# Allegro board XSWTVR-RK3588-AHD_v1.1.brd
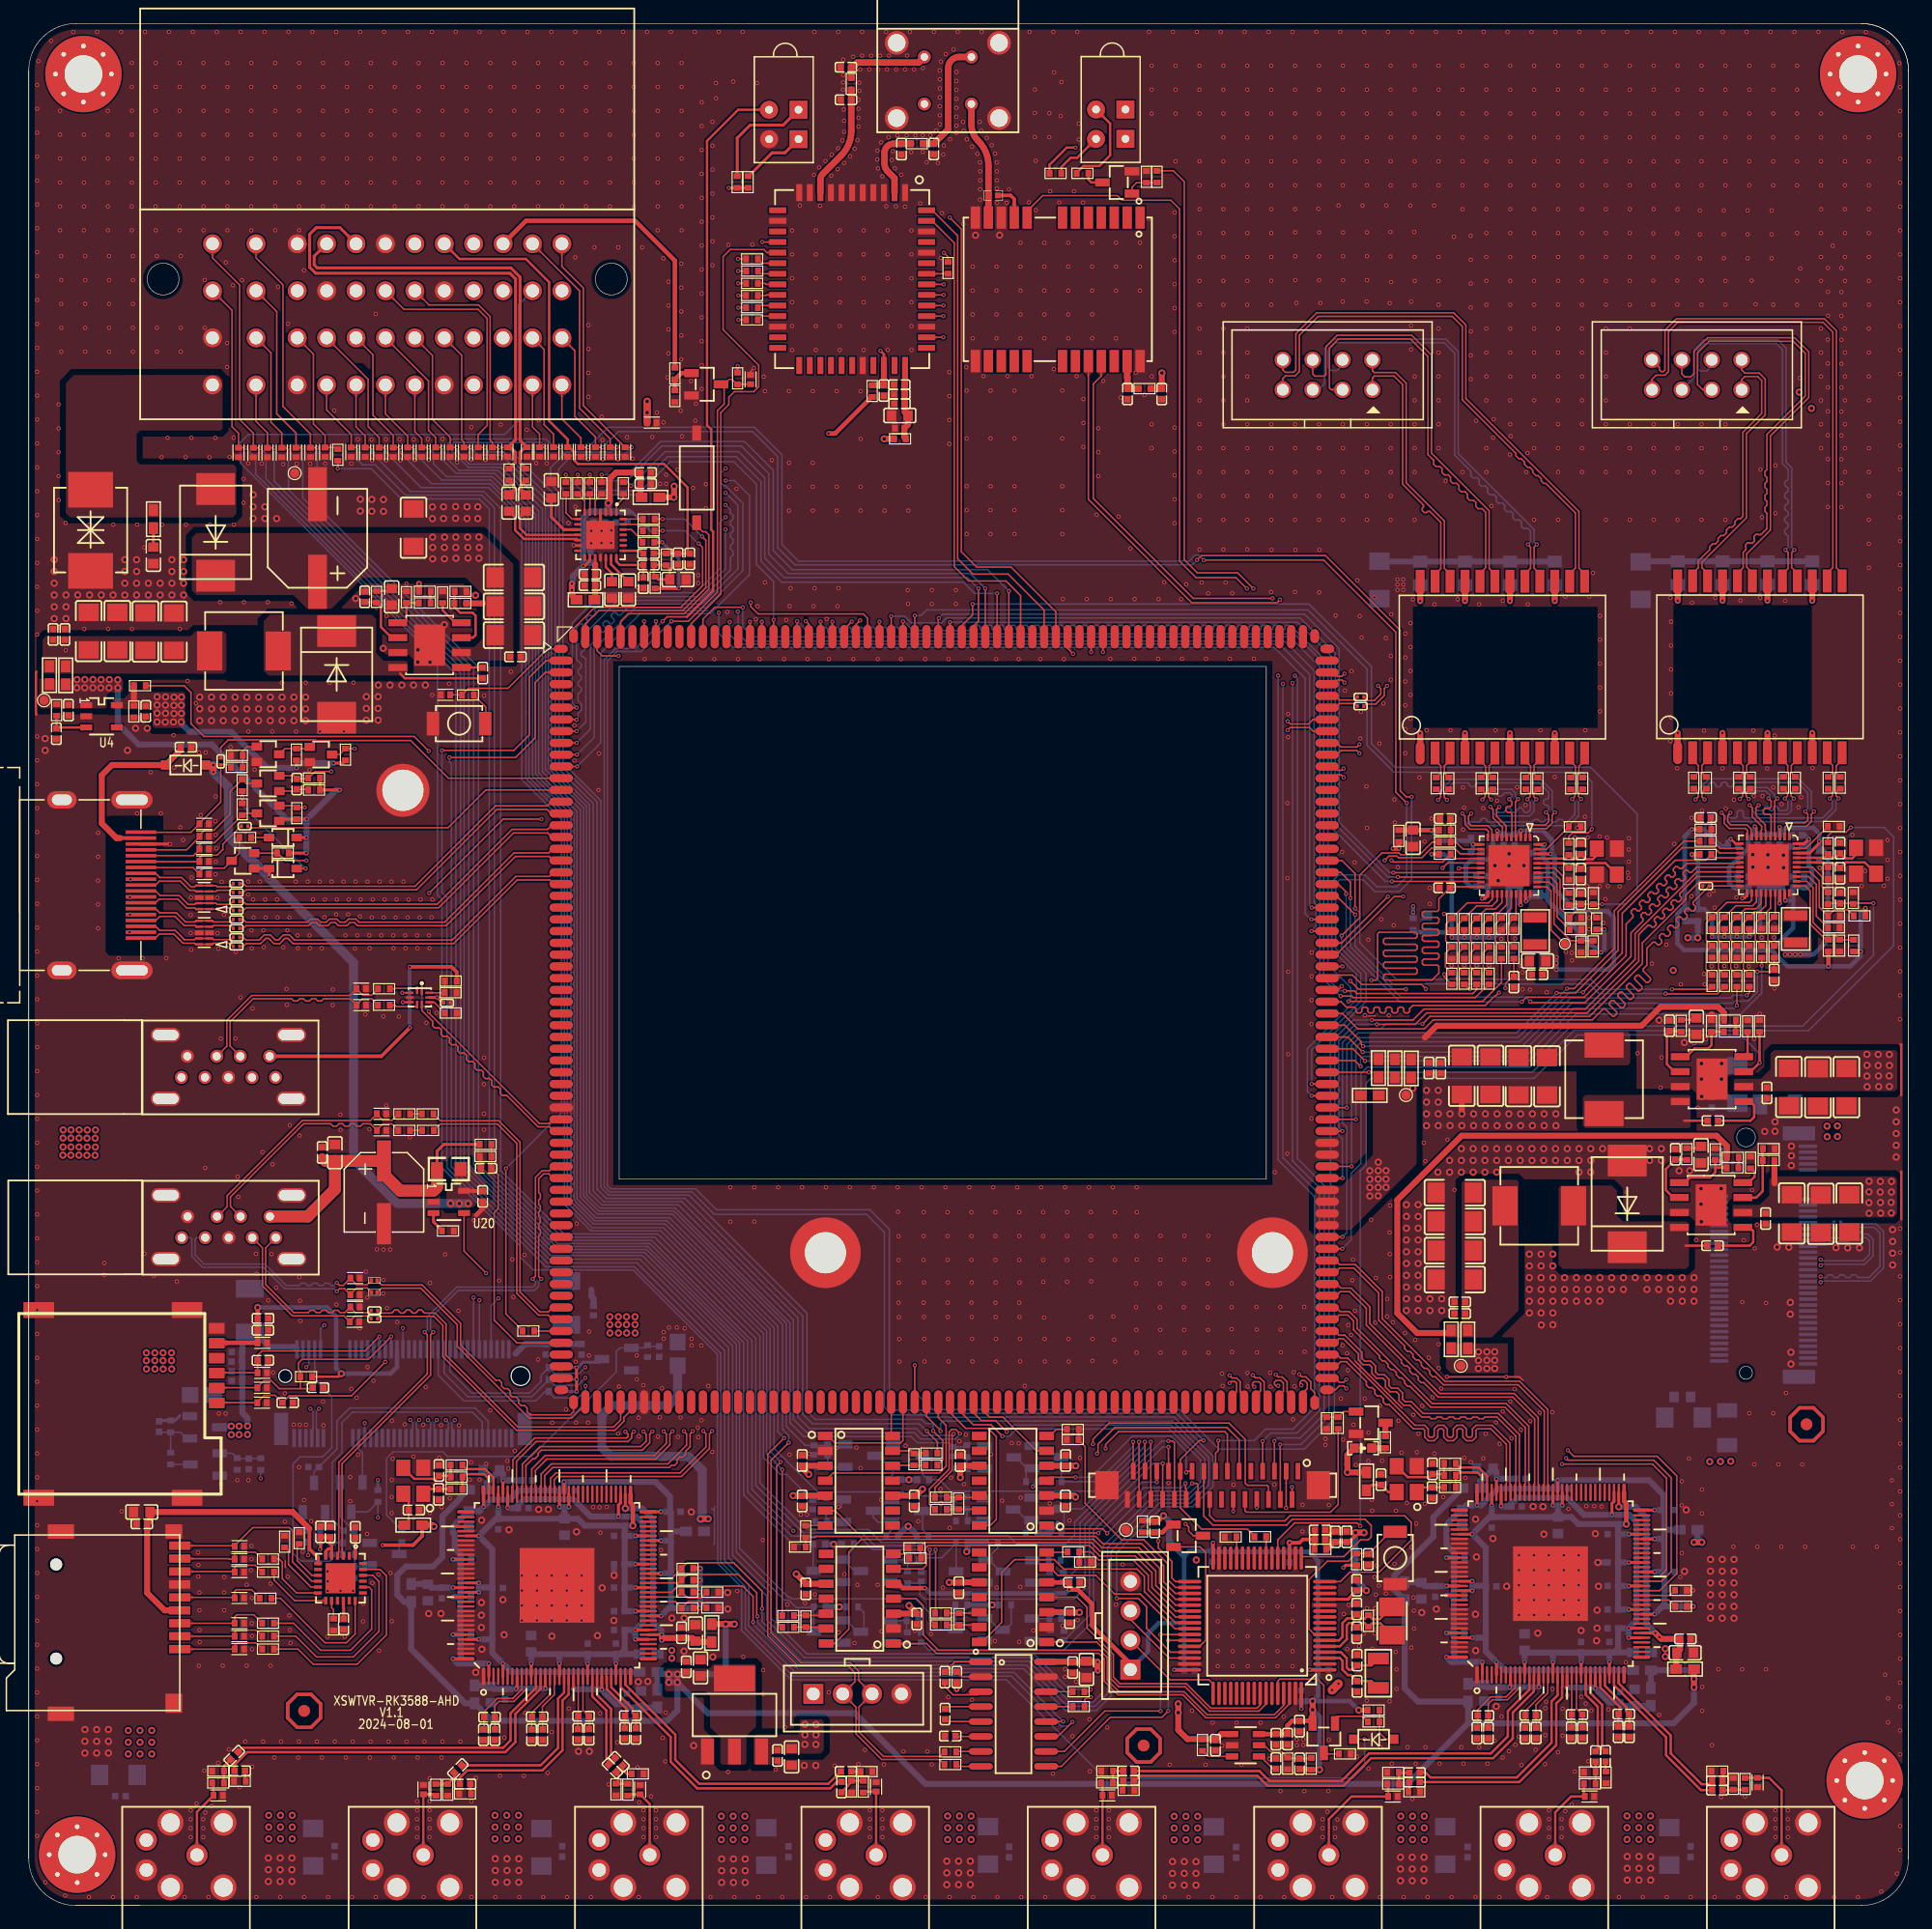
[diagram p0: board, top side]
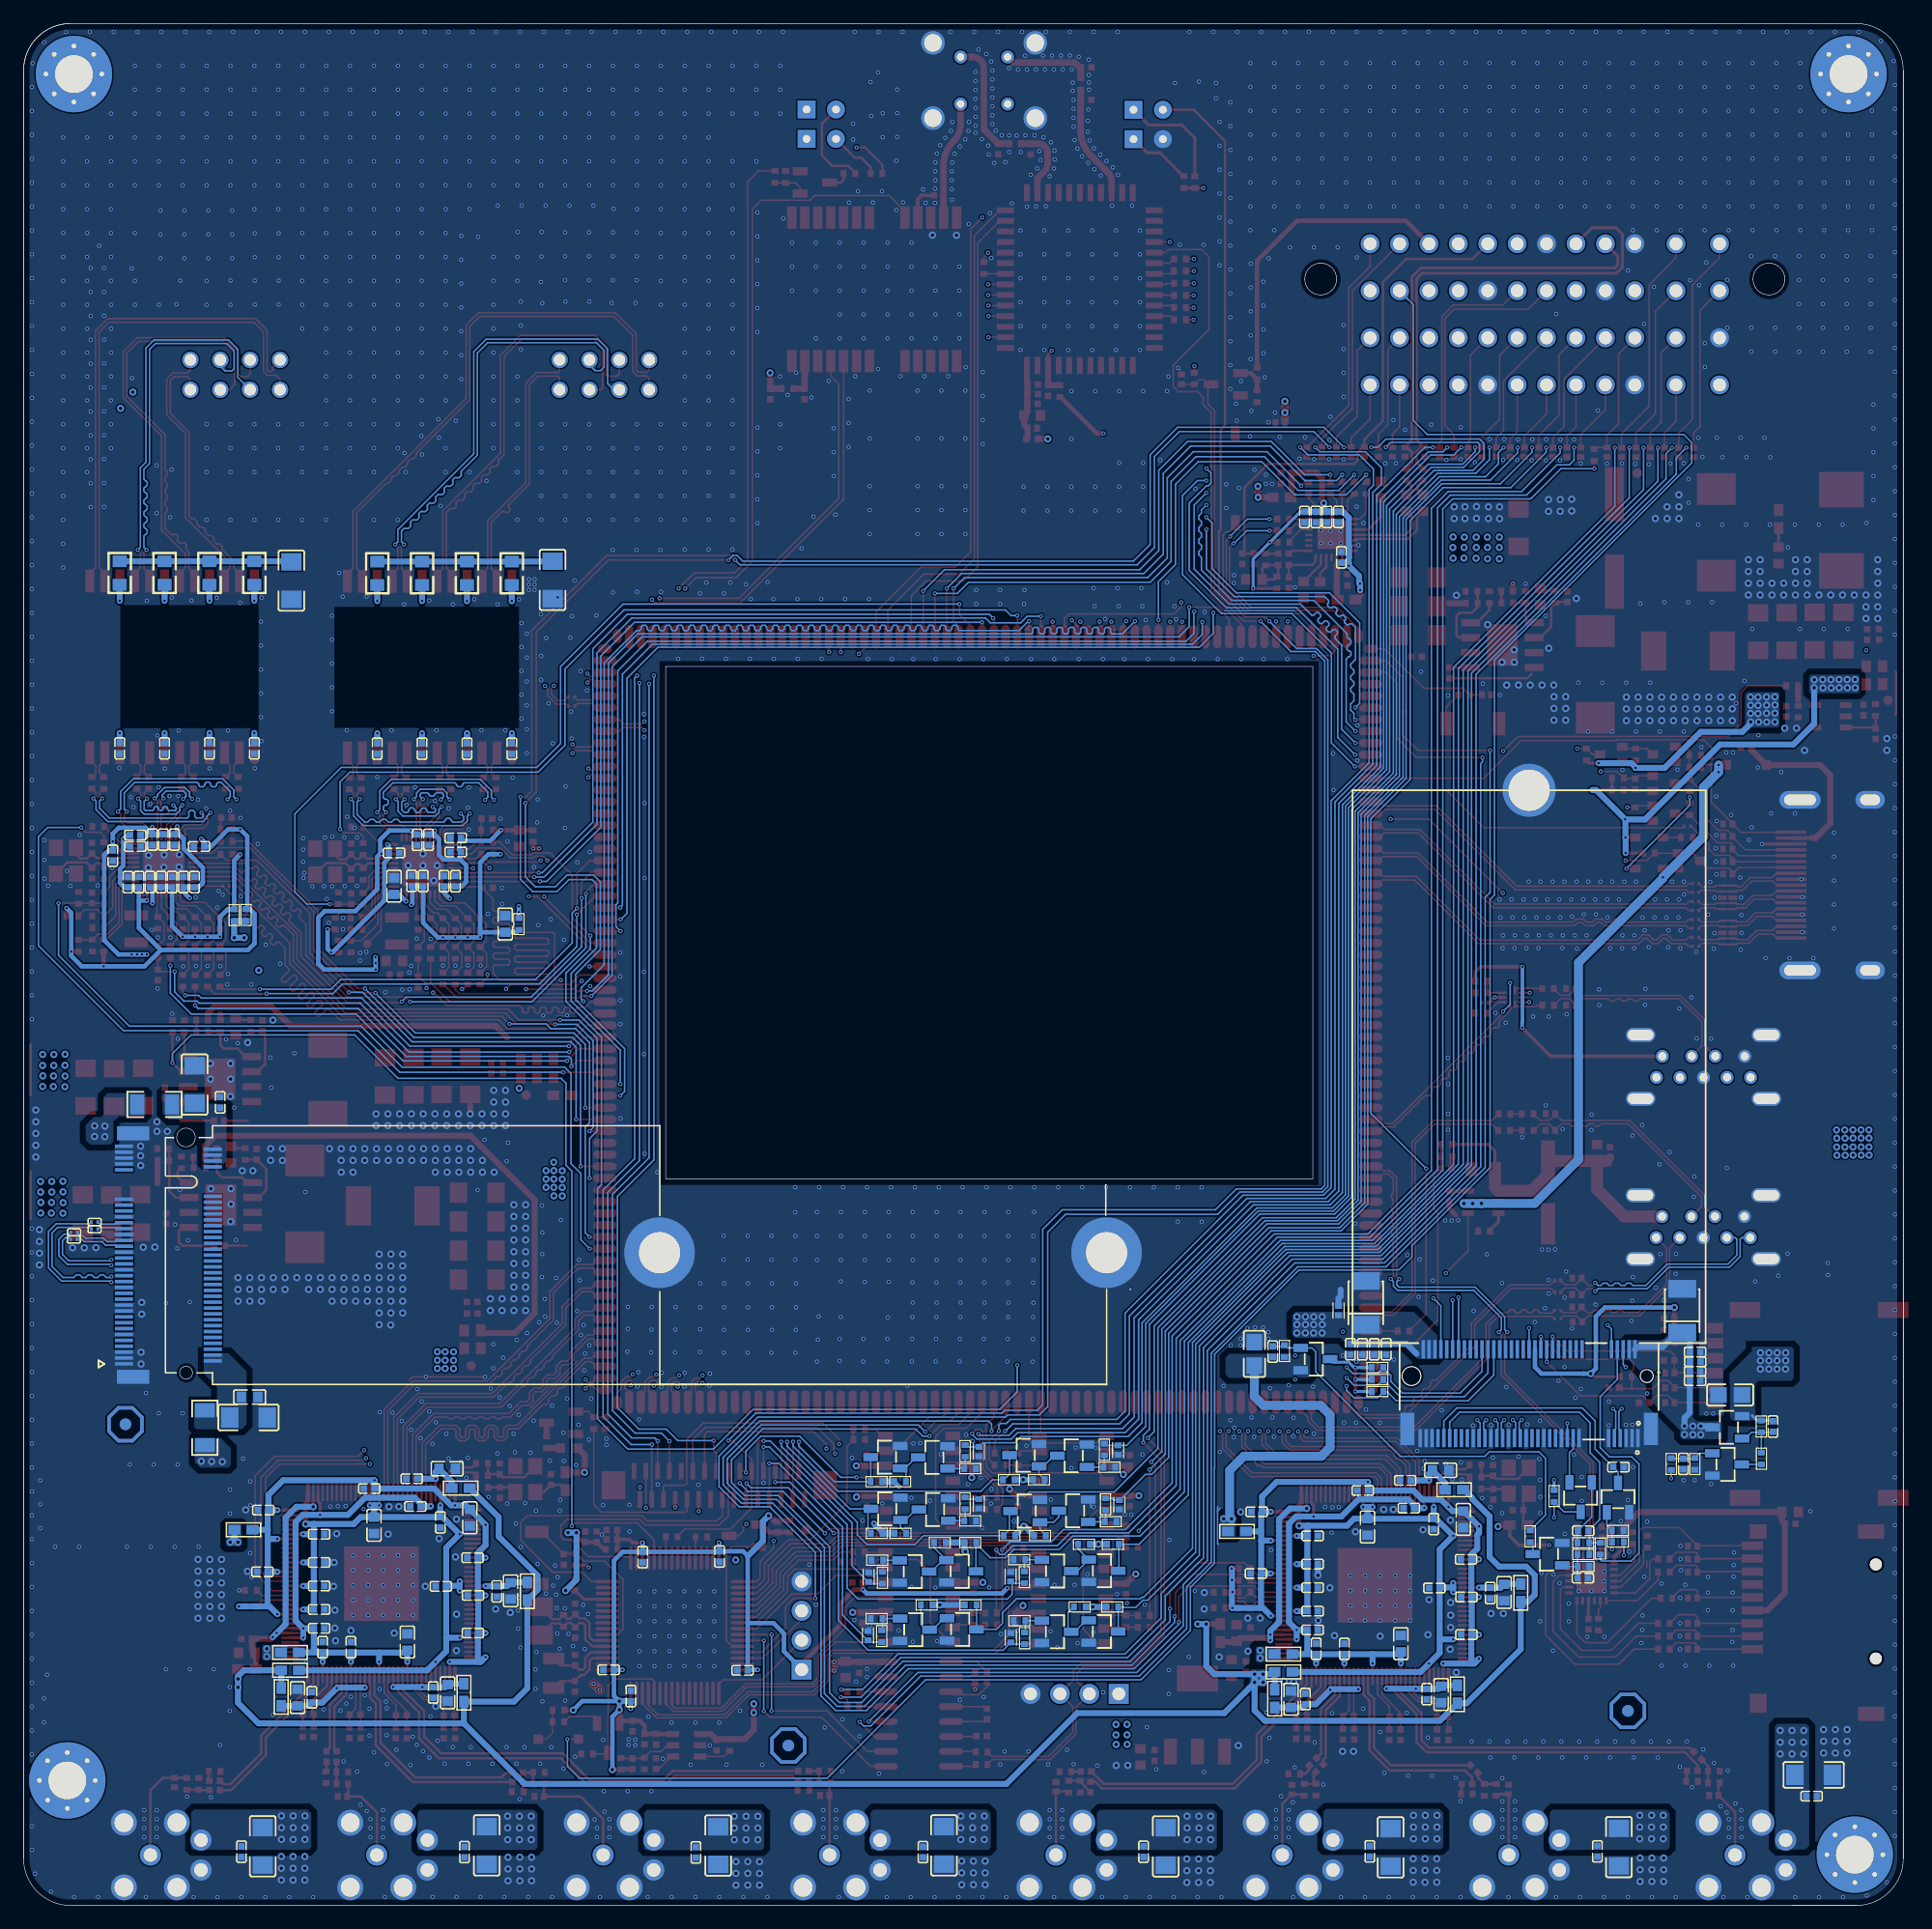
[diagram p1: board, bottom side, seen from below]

Outline 159.78 x 160 mm; copper layers: TOP, GND02, L3, POW04, GND05, BOTTOM. Coordinates in mm from the lower left corner of the outline.
Outline path: 0,156 0,4 ; 0,156 arc(1.17,158.83) 4,160 155.78,160 ; 0,156 0,4 ; 0,4 arc(1.17,1.17) 4,0 ; 4,0 9.4,0 ; 4,0 9.4,0 ; 9.4,0 155.78,0 arc(158.61,1.17) 159.78,4 ; 155.78,160 arc(158.61,158.83) 159.78,156 ; 155.78,160 arc(158.61,158.83) 159.78,156 ; 159.78,156 159.78,4 ; 159.78,156 159.78,4 ; 50.19,105.34 50.19,61.77 105.2,61.77 105.2,105.34 50.19,105.34

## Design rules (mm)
constraint set DEFAULT: min track width 0.102
net group 5G_USB: nets 5G_USB_DM 5G_USB_DP
net group HDMI0_TX0N_PORT: nets HDMI0_TX0N_PORT HDMI0_TX0N_PORT/EDP0_TX_D0N
net group HDMI0_TX0P_PORT: nets HDMI0_TX0P_PORT HDMI0_TX0P_PORT/EDP0_TX_D0P
net group HDMI0_TX1N_PORT: nets HDMI0_TX1N_PORT HDMI0_TX1N_PORT/EDP0_TX_D1N
net group HDMI0_TX1P_PORT: nets HDMI0_TX1P_PORT HDMI0_TX1P_PORT/EDP0_TX_D1P
net group HDMI0_TX2N_PORT: nets HDMI0_TX2N_PORT HDMI0_TX2N_PORT/EDP0_TX_D2N
net group HDMI0_TX2P_PORT: nets HDMI0_TX2P_PORT HDMI0_TX2P_PORT/EDP0_TX_D2P
net group HDMI0_TX3N_PORT: nets HDMI0_TX3N_PORT HDMI0_TX3N_PORT/EDP0_TX_D3N
net group HDMI0_TX3P_PORT: nets HDMI0_TX3P_PORT HDMI0_TX3P_PORT/EDP0_TX_D3P
net group LAN0_A: nets LAN0_A+ LAN0_A-
net group LAN0_B: nets LAN0_B+ LAN0_B-
net group LAN0_C: nets LAN0_C+ LAN0_C-
net group LAN0_D: nets LAN0_D+ LAN0_D-
net group LAN1_A: nets LAN1_A+ LAN1_A-
net group LAN1_B: nets LAN1_B+ LAN1_B-
net group LAN1_C: nets LAN1_C+ LAN1_C-
net group LAN1_D: nets LAN1_D+ LAN1_D-
net group N17604219: nets N17604219 N17604223
net group N17604225: nets N17604225 N17604227
net group PCIE20_0_RXN/SATA30_0_RXN: nets PCIE20_0_RXN/SATA30_0_RXN SATA0_RXN
net group PCIE20_0_RXP/SATA30_0_RXP: nets PCIE20_0_RXP/SATA30_0_RXP SATA0_RXP
net group PCIE20_0_TXN/SATA30_0_TXN: nets PCIE20_0_TXN/SATA30_0_TXN SATA0_TXN
net group PCIE20_0_TXP/SATA30_0_TXP: nets PCIE20_0_TXP/SATA30_0_TXP SATA0_TXP
net group PCIE20_2_REFCLK: nets PCIE20_2_REFCLKN PCIE20_2_REFCLKP
net group PCIE20_2_RXN/SATA30_2_RX: nets PCIE20_2_RXN/SATA30_2_RXN PCIE20_2_RXP/SATA30_2_RXP
net group PCIE20_2_TX: nets N17473177 N17473180
net group PCIE20_2_TXN/SATA30_2_TX: nets PCIE20_2_TXN/SATA30_2_TXN PCIE20_2_TXP/SATA30_2_TXP
net group PHY0_MDI0+: nets PHY0_MDI0+ PHY0_MDI_0+
net group PHY0_MDI0-: nets PHY0_MDI0- PHY0_MDI_0-
net group PHY0_MDI1+: nets PHY0_MDI1+ PHY0_MDI_1+
net group PHY0_MDI1-: nets PHY0_MDI1- PHY0_MDI_1-
net group PHY0_MDI2+: nets PHY0_MDI2+ PHY0_MDI_2+
net group PHY0_MDI2-: nets PHY0_MDI2- PHY0_MDI_2-
net group PHY0_MDI3+: nets PHY0_MDI3+ PHY0_MDI_3+
net group PHY0_MDI3-: nets PHY0_MDI3- PHY0_MDI_3-
net group PHY1_MDI0: nets PHY1_MDI0+ PHY1_MDI0-
net group PHY1_MDI1: nets PHY1_MDI1+ PHY1_MDI1-
net group PHY1_MDI2: nets PHY1_MDI2+ PHY1_MDI2-
net group PHY1_MDI3: nets PHY1_MDI3+ PHY1_MDI3-
net group PHY1_MDI_0: nets PHY1_MDI_0+ PHY1_MDI_0-
net group PHY1_MDI_1: nets PHY1_MDI_1+ PHY1_MDI_1-
net group PHY1_MDI_2: nets PHY1_MDI_2+ PHY1_MDI_2-
net group PHY1_MDI_3: nets PHY1_MDI_3+ PHY1_MDI_3-
net group SDMMC_CMD: nets N17735212 SDMMC_CMD
net group SDMMC_D0: nets N17735257 SDMMC_D0
net group SDMMC_D1: nets N17735222 SDMMC_D1
net group SDMMC_D2: nets N17735246 SDMMC_D2
net group SDMMC_D3: nets N17735210 SDMMC_D3
net group TYPEC0_OTG_DM: nets N17570124 TYPEC0_OTG_DM
net group TYPEC0_OTG_DP: nets N17570191 TYPEC0_OTG_DP
net group TYPEC0_SSRX1: nets TYPEC0_SSRX1N TYPEC0_SSRX1P
net group TYPEC0_SSTX1: nets TYPEC0_SSTX1N TYPEC0_SSTX1P
net group USB20_HOST0: nets USB20_HOST0_DM USB20_HOST0_DP
net group USB20_HOST1: nets USB20_HOST1_DM USB20_HOST1_DP
net group USB30_HOST0_SSRX: nets USB30_HOST0_SSRXN USB30_HOST0_SSRXP
net group USB30_HOST0_SSTX: nets USB30_HOST0_SSTXN USB30_HOST0_SSTXP
net group USB30_OTG0: nets USB30_OTG0_DM USB30_OTG0_DP
net group USB30_OTG1: nets DEBUG_DM0 DEBUG_DP0
net group GMAC0_RXCLK: nets GMAC0_RXCLK
net group GMAC0_RXD0: nets GMAC0_RXD0
net group GMAC0_RXD1: nets GMAC0_RXD1
net group GMAC0_RXD2: nets GMAC0_RXD2
net group GMAC0_RXD3: nets GMAC0_RXD3
net group GMAC0_RXDV_CRS: nets GMAC0_RXDV_CRS
net group GMAC1_RXCLK: nets GMAC1_RXCLK
net group GMAC1_RXD0: nets GMAC1_RXD0
net group GMAC1_RXD1: nets GMAC1_RXD1
net group GMAC1_RXD2: nets GMAC1_RXD2
net group GMAC1_RXD3: nets GMAC1_RXD3
net group GMAC1_RXDV_CRS: nets GMAC1_RXDV_CRS

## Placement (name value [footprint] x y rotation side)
C1  100nF  [C0402]  143.16 66.72 0 top
C2  47uF  [C1206]  121.81 70.54 270 top
C3  47uF  [C1206]  129.06 70.5 270 top
C4  47uF  [C1206]  124.25 70.54 270 top
C5  47uF  [C1206]  126.64 70.51 270 top
C6  1uF  [C0402]  120.02 71.2 270 top
C7  100nF  [C0402]  119.02 71.2 270 top
C8  10uF  [C1206]  154.5 69.57 270 top
C9  10uF  [C1206]  152.08 69.55 270 top
C10  10uF  [C1206]  149.62 69.59 270 top
C11  100nF  [C0402]  147.75 69.08 270 top
C12  22pF  [C0402]  139.47 74.79 90 top
C13  3.3nF  [C0603]  141.75 74.75 270 top
C14  100nF  [C0402]  38.59 104.79 90 top
C15  47uF  [C1206]  7.53 108.34 90 top
C16  47uF  [C1206]  5.09 108.34 90 top
C17  47uF  [C1206]  12.34 108.3 90 top
C18  47uF  [C1206]  9.92 108.31 90 top
C19  1uF  [C0402]  3.07 108.06 90 top
C20  100nF  [C0402]  2.07 108.06 90 top
C21  10uF  [C1206]  41.24 112.9 0 top
C22  10uF  [C1206]  41.24 110.45 0 top
C23  10uF  [C1206]  41.24 108 0 top
C24  100nF  [C0402]  41.37 106.16 0 top
C25  100nF  [C0402]  2.35 99.62 270 top
C26  10uF  [C0402]  3.37 101.63 270 top
C27  4.7uF  [C0402]  9.95 101.52 270 top
C28  47pF  [C0402]  28.56 111.26 90 top
C29  4.7nF  [C0603]  30.85 111.26 270 top
C30  100nF  [C0402]  143.13 56.1 0 top
C31  47uF  [C1206]  121.21 55.68 180 top
C32  47uF  [C1206]  121.21 58.15 180 top
C33  47uF  [C1206]  121.21 53.21 180 top
C34  47uF  [C1206]  121.21 60.6 180 top
C35  1uF  [C0402]  121.65 51.32 180 top
C36  100nF  [C0402]  121.64 50.33 180 top
C37  10uF  [C1206]  152.33 58.8 270 top
C38  10uF  [C1206]  149.87 58.84 270 top
C39  10uF  [C1206]  154.75 58.83 270 top
C40  100nF  [C0402]  147.64 58.4 270 top
C41  100UF/50V  [SMD_D8XL10_5MM]  24.55 116.26 90 top
C42  10uF  [C1206]  32.71 117.14 90 top
C43  1uF  [C0603]  10.6 114.78 270 top
C44  22pF  [C0402]  139.97 63.87 90 top
C45  3.3nF  [C0603]  142.15 63.83 270 top
C46  39pF  [C0402]  108.02 12.05 90 top
C51  10uF  [C0402]  106.02 14.14 270 top
C52  100nF  [C0402]  107 14.14 90 top
C56  10UF  [C0402]  100.87 13.63 90 top
C57  10nF  [C0402]  106.02 12.06 90 top
C60  12pF  [C0402]  112.91 18.63 270 top
C61  12pF  [C0402]  112.91 20.86 90 top
C62  100nF  [C0402]  113.86 29.43 270 top
C63  12pF  [C0402]  112.89 23.2 270 top
C64  12pF  [C0402]  112.89 25.21 90 top
C65  100nF  [C0402]  112.88 27.22 90 top
C66  100nF  [C0402]  100.62 29.67 270 bottom
C67  100nF  [C0402]  110.04 20.03 0 bottom
C68  100nF  [C0402]  108.16 17.8 90 bottom
C69  100nF  [C0402]  98.66 19.99 0 bottom
C70  100nF  [C0402]  107.15 29.62 270 bottom
C71  1uF  [C0402]  109.77 31.92 0 top
C72  100nF  [C0402]  109.77 31.12 0 top
C73  100nF  [C0402]  112.04 31.34 90 top
C74  1uF  [C0402]  111.07 31.34 90 top
C75  100nF  [C0402]  75.49 24.35 270 top
C76  100nF  [C0402]  108.02 15.25 90 top
C79  220UF/6.3V  [T_3528]  18.79 50.57 90 bottom
C80  10pF  [C0402]  17.68 46.24 0 bottom
C81  33pF  [C0402]  17.7 47.06 0 bottom
C82  100nF  [C0402]  17.7 45.41 0 bottom
C83  1uF  [C0402]  17.7 44.61 0 bottom
C84  10nF  [C0402]  24.21 37.27 0 bottom
C85  220nF  [C0201]  113.21 101.97 0 top
C86  220nF  [C0201]  113.21 102.75 0 top
C87  10pF  [C0402]  43.95 47.29 270 bottom
C88  1uF  [C0402]  47 47.29 270 bottom
C89  220UF/6.3V  [T_3528]  45.69 51.23 90 bottom
C91  33pF  [C0402]  44.96 47.29 270 bottom
C92  100nF  [C0402]  45.97 47.29 270 bottom
C96  100nF  [C0402]  19.91 48.91 0 top
C97  33pF  [C0402]  19.91 49.91 0 top
C98  33pF  [C0402]  19.9 46.35 0 top
C99  33pF  [C0402]  24.59 44.02 0 top
C100  33pF  [C0402]  22.01 42.75 0 top
C105  10uF  [C0805]  14.71 43.4 0 bottom
C106  100nF  [C0402]  11.08 40.72 270 bottom
C107  10uF  [C0805]  55.16 46.89 90 bottom
C108  100nF  [C0402]  53.59 47.09 90 bottom
C109  100nF  [C0402]  18.7 37.54 270 bottom
C110  100nF  [C0402]  27.24 27.83 180 bottom
C111  100nF  [C0402]  117.8 11.29 0 top
C112  100nF  [C0402]  143.53 10.6 180 top
C113  100nF  [C0402]  123.1 14.65 90 top
C114  100nF  [C0402]  123.62 16.15 0 top
C115  100nF  [C0402]  127.66 16.18 0 top
C116  100nF  [C0402]  128.14 14.66 90 top
C117  100nF  [C0402]  131.12 14.69 90 top
C118  100nF  [C0402]  131.61 16.23 0 top
C119  100nF  [C0402]  93.49 11.43 0 top
C120  100nF  [C0402]  93.49 10.63 0 top
C121  100nF  [C0402]  117.8 10.49 0 top
C122  100nF  [C0402]  133.18 12.66 90 top
C123  100nF  [C0402]  134.03 12.67 90 top
C124  100nF  [C0402]  143.53 9.81 180 top
C125  100nF  [C0402]  114.94 36.21 90 top
C126  100nF  [C0402]  127.19 14.66 90 top
C127  100nF  [C0402]  124.07 14.66 90 top
C128  100nF  [C0402]  135.11 14.77 90 top
C129  100nF  [C0402]  132.08 14.69 90 top
C130  100nF  [C0402]  135.58 16.27 0 top
C131  15pF/NC  [C0402]  119.29 35.1 270 top
C132  15pF/NC  [C0402]  119.31 37.12 90 top
C133  100nF  [C0402]  136.06 14.77 90 top
C134  10uF  [C0603]  64.84 12.63 270 top
C135  100nF  [C0402]  63.65 12.75 270 top
C136  100nF  [C0402]  55.89 20.29 90 top
C137  10uF  [C0603]  57.1 20.2 90 top
C138  10uF  [C0603]  127.16 22.4 90 bottom
C139  100nF  [C0402]  134.65 23.56 180 bottom
C140  100nF  [C0402]  134.36 21.96 90 bottom
C141  100nF  [C0402]  126.47 33.92 0 bottom
C142  100nF  [C0402]  131.96 21.95 90 bottom
C143  10uF  [C0603]  121.85 32.97 270 bottom
C144  100nF  [C0402]  121.58 26.36 0 bottom
C145  100nF  [C0402]  130.4 35.44 0 bottom
C146  100nF  [C0402]  139.47 28.36 0 bottom
C147  100nF  [C0402]  121.61 29.56 0 bottom
C148  100nF  [C0402]  121.58 23.16 0 bottom
C149  100nF  [C0402]  139.4 33.61 0 bottom
C150  10uF  [C0603]  123.77 37.14 180 bottom
C151  100nF  [C0402]  126.78 36.28 0 bottom
C152  10uF  [C0603]  118.38 26.75 270 bottom
C153  100nF  [C0402]  119.56 26.7 270 bottom
C154  10uF  [C0603]  129.99 32.32 270 bottom
C155  100nF  [C0402]  134.65 29.16 180 bottom
C156  100nF  [C0402]  124.3 27.13 0 bottom
C157  100nF  [C0402]  124.36 32.57 270 bottom
C158  100nF  [C0402]  134.65 25.16 180 bottom
C159  100nF  [C0402]  134.65 27.16 180 bottom
C160  100nF  [C0402]  134.65 31.56 180 bottom
C161  10uF  [C0603]  123.73 18.08 270 bottom
C162  100nF  [C0402]  124.95 18.11 270 bottom
C163  10uF  [C0603]  136.49 17.67 90 bottom
C164  100nF  [C0402]  135.27 17.7 90 bottom
C165  10uF  [C0603]  140.8 21.48 0 top
C166  100nF  [C0402]  140.81 22.66 0 top
C167  100nF  [C0402]  83.33 4.54 270 bottom
C168  47uF  [C1206]  81.54 5.11 270 bottom
C169  100nF  [C0402]  102.63 4.51 270 bottom
C170  47uF  [C1206]  100.73 5.1 270 bottom
C171  100nF  [C0402]  122.3 4.54 270 bottom
C172  47uF  [C1206]  120.41 5.1 270 bottom
C173  100nF  [C0402]  141.26 4.57 270 bottom
C174  47uF  [C1206]  139.45 5.03 270 bottom
C175  100nF  [C0402]  17.47 12.73 45 top
C176  100nF  [C0402]  17.94 11.45 180 top
C177  100nF  [C0402]  36.48 11.6 45 top
C178  100nF  [C0402]  37.09 10.32 180 top
C179  100nF  [C0402]  50.17 12.22 135 top
C180  100nF  [C0402]  69.1 10.07 90 top
C181  100nF  [C0402]  39.17 16.01 0 top
C182  100nF  [C0402]  42.74 14.52 90 top
C183  100nF  [C0402]  43.22 16.04 0 top
C184  100nF  [C0402]  43.69 14.52 90 top
C185  100nF  [C0402]  47.16 16.09 0 top
C186  100nF  [C0402]  49.61 11.67 135 top
C187  100nF  [C0402]  69.47 11.4 180 top
C188  100nF  [C0402]  38.65 14.51 90 top
C189  100nF  [C0402]  39.62 14.52 90 top
C190  100nF  [C0402]  46.67 14.55 90 top
C191  100nF  [C0402]  32.74 33.62 0 top
C192  100nF  [C0402]  47.63 14.55 90 top
C193  100nF  [C0402]  50.66 14.63 90 top
C194  100nF  [C0402]  51.14 16.13 0 top
C195  100nF  [C0402]  51.61 14.63 90 top
C196  15pF/NC  [C0402]  34.84 34.96 270 top
C197  15pF/NC  [C0402]  34.87 36.99 90 top
C198  10uF  [C0603]  42.71 22.26 90 bottom
C199  100nF  [C0402]  47.51 21.81 90 bottom
C200  100nF  [C0402]  50.2 23.42 180 bottom
C201  100nF  [C0402]  42.03 33.78 0 bottom
C202  100nF  [C0402]  49.91 21.82 90 bottom
C203  10uF  [C0603]  37.4 32.83 270 bottom
C204  100nF  [C0402]  37.13 26.22 0 bottom
C205  100nF  [C0402]  54.95 33.47 0 bottom
C206  100nF  [C0402]  37.16 29.42 0 bottom
C207  100nF  [C0402]  45.94 35.28 0 bottom
C208  100nF  [C0402]  37.14 23.02 0 bottom
C209  100nF  [C0402]  55.03 28.22 0 bottom
C210  10uF  [C0603]  39.28 17.94 270 bottom
C211  100nF  [C0402]  40.5 17.97 270 bottom
C212  10uF  [C0603]  33.93 26.61 270 bottom
C213  100nF  [C0402]  35.11 26.56 270 bottom
C214  10uF  [C0603]  45.54 32.18 270 bottom
C215  100nF  [C0402]  39.91 32.43 270 bottom
C216  100nF  [C0402]  50.2 27.02 180 bottom
C217  100nF  [C0402]  50.2 29.02 180 bottom
C218  100nF  [C0402]  39.86 26.99 0 bottom
C219  100nF  [C0402]  50.2 31.42 180 bottom
C220  100nF  [C0402]  50.2 25.02 180 bottom
C221  10uF  [C0603]  52.04 17.53 90 bottom
C222  100nF  [C0402]  50.82 17.56 90 bottom
C223  10uF  [C0603]  56.67 23.17 90 top
C224  100nF  [C0402]  55.49 23.19 90 top
C225  10uF  [C0603]  39.32 37 180 bottom
C226  100nF  [C0402]  42.33 36.14 0 bottom
C227  100nF  [C0402]  7.79 9.3 180 bottom
C228  47uF  [C1206]  7.62 11.1 180 bottom
C229  100nF  [C0402]  26 4.6 270 bottom
C230  47uF  [C1206]  24.17 4.96 270 bottom
C231  100nF  [C0402]  45.35 4.6 270 bottom
C232  47uF  [C1206]  43.58 4.94 270 bottom
C233  100nF  [C0402]  64.58 4.57 270 bottom
C234  47uF  [C1206]  62.69 5.02 270 bottom
C235  220nF  [C0201]  17.66 81.55 180 top
C236  220nF  [C0201]  17.66 82.31 180 top
C237  220nF  [C0201]  17.66 83.07 180 top
C238  220nF  [C0201]  17.66 83.83 180 top
C239  220nF  [C0201]  17.66 84.59 180 top
C240  220nF  [C0201]  17.66 85.36 180 top
C241  220nF  [C0201]  17.66 86.12 180 top
C242  220nF  [C0201]  17.66 86.88 180 top
C243  100pF  [C0402]  22.79 95.34 90 top
C244  1uF  [C0402]  13.36 98.48 0 top
C245  1uF  [C0201]  18.35 91.76 180 top
C246  1uF  [C0201]  16.32 97.27 270 top
C247  22uF  [C0603]  74.05 126.67 180 top
C248  100nF  [C0402]  74 129.29 180 top
C249  100pF  [C0402]  74.02 127.67 180 top
C250  10pF  [C0402]  74 128.49 180 top
C251  NC  [C0402]  69.47 153.51 180 top
C252  NC  [C0402]  69.46 156.29 180 top
C253  NC  [C0402]  74.18 149.32 270 top
C254  NC  [C0402]  76.93 149.34 270 top
C255  4.7uF  [C0402]  72.69 128.8 270 top
C256  100nF  [C0402]  93.4 128.5 90 top
C257  100nF  [C0402]  96.31 128.5 90 top
C258  18pF  [C0402]  131.93 89.82 90 top
C259  18pF  [C0402]  131.93 87.69 270 top
C260  10nF  [C0402]  118.27 98.35 270 bottom
C261  10nF  [C0402]  122.08 98.35 270 bottom
C262  10nF  [C0402]  125.9 98.35 270 bottom
C263  10nF  [C0402]  129.71 98.35 270 bottom
C264  DNP  [C0402]  131.93 85.58 90 top
C265  1000pF  [C1206]  114.81 112.7 270 bottom
C266  4.7uF  [C0603]  118.84 83.44 90 bottom
C267  1uF  [C0402]  125.81 87.1 90 bottom
C268  100nF  [C0402]  126.8 87.11 90 bottom
C269  4.7uF  [C0603]  117.67 90.73 270 top
C270  100nF  [C0402]  123.04 90.76 0 bottom
C271  100nF  [C0402]  123.04 89.56 0 bottom
C272  4.7uF  [C0603]  128.29 86.66 90 bottom
C273  100nF  [C0402]  128.29 89.49 180 bottom
C274  3pF  [C0402]  120.35 86.52 180 top
C275  4.7uF  [C0603]  128.26 80.3 180 top
C276  100nF  [C0402]  128.22 79.14 180 top
C277  100nF  [C0402]  124.03 87.09 90 bottom
C278  100nF  [C0402]  120.39 92.4 180 top
C279  100nF  [C0402]  125.36 90.6 270 bottom
C280  100nF  [C0402]  126.32 90.6 270 bottom
C281  100nF  [C0402]  123.07 87.09 90 bottom
C282  DNP  [C0402]  126.25 78.51 270 top
C283  18pF  [C0402]  153.96 89.89 90 top
C284  18pF  [C0402]  153.96 87.76 270 top
C285  10nF  [C0402]  140.16 98.38 270 bottom
C286  10nF  [C0402]  143.97 98.38 270 bottom
C287  10nF  [C0402]  147.79 98.38 270 bottom
C288  10nF  [C0402]  151.6 98.38 270 bottom
C289  DNP  [C0402]  153.96 85.65 90 top
C290  1000pF  [C1206]  137.01 112.64 270 bottom
C291  4.7uF  [C0402]  148.09 87.01 90 bottom
C292  1uF  [C0402]  147.15 87.01 90 bottom
C293  100nF  [C0402]  149.03 87.01 90 bottom
C294  4.7uF  [C0402]  144.86 90.04 0 bottom
C295  100nF  [C0402]  150.28 91 180 bottom
C296  100nF  [C0402]  149.97 87.01 90 bottom
C297  3pF  [C0201]  142.56 86.67 180 top
C298  4.7uF  [C0402]  150.91 87.01 90 bottom
C299  100nF  [C0402]  150.28 90.04 180 bottom
C300  100nF  [C0402]  142.53 92.49 180 top
C301  4.7uF  [C0402]  146.19 87.01 90 bottom
C302  100nF  [C0402]  147.89 90.62 270 bottom
C303  100nF  [C0402]  146.95 90.62 270 bottom
C304  DNP  [C0402]  148.36 79.11 270 top
C305  100nF  [C0402]  148.83 90.62 270 bottom
C306  100nF  [C0402]  152.2 89.25 270 bottom
C307  100nF  [C0402]  145.25 87.01 90 bottom
C308  1uF  [C0402]  38.58 60.29 270 top
C309  100nF  [C0201]  29.38 49.89 180 top
C310  120uF  [SMD_D6_3XL7_7]  30.19 60.63 270 top
C311  10uF  [C0603]  26.03 64 90 top
C312  100nF  [C0402]  24.94 64.02 90 top
C313  100nF  [C0201]  29.38 50.59 180 top
C314  100nF  [C0402]  38.88 62.67 180 top
C321  100nF  [C0402]  25.61 31.75 90 top
C322  4.7uF  [C0402]  24.81 31.76 90 top
C323  10uF  [C0603]  9.61 33.45 180 top
C324  100nF  [C0402]  9.61 32.44 180 top
C325  10uF  [C0603]  55.19 112.73 0 top
C326  1uF  [C0402]  52.69 114.94 180 top
C327  100pF  [C0402]  56.19 114.49 270 top
C328  1uF  [C0402]  52.24 112.46 90 top
C329  1uF  [C0402]  52.69 113.97 180 top
C330  8.2pF  [C0402]  55.2 114.49 270 top
C331  4.7uF  [C0402]  49.94 118.05 270 bottom
C332  100nF  [C0402]  50.9 118.04 270 bottom
C333  100nF  [C0402]  47.76 114.62 90 bottom
C334  100nF  [C0402]  47.7 113.18 180 top
C335  4.7uF  [C0402]  47.7 112.22 180 top
C336  4.7uF  [C0402]  48.01 118.05 270 bottom
C337  100nF  [C0402]  48.98 118.05 270 bottom
C338  10uF  [C0603]  50.97 111.85 270 top
C339  10uF  [C0603]  49.57 111.84 270 top
C340  10uF  [C0603]  44.42 120.37 90 top
C341  4.7uF  [C0402]  52.44 120.88 0 top
C342  100nF  [C0402]  52.44 121.83 0 top
C343  47uF  [C0603]  40.83 119.23 90 top
C344  47uF  [C0603]  42.24 119.22 90 top
C345  100nF  [C0402]  77.88 19.42 90 top
C346  100nF  [C0402]  77.89 16.27 270 top
C347  100nF  [C0402]  78.89 19.41 90 top
C348  100nF  [C0402]  78.33 14.41 180 top
C349  10uF  [C0603]  89.91 20.07 270 top
C350  100nF  [C0402]  88.74 20.23 90 top
C355  10nF  [C0201]  153.74 57.5 180 bottom
C356  10nF  [C0201]  153.74 58.11 180 bottom
C357  10nF  [C0201]  155.48 57.23 180 bottom
C358  10nF  [C0201]  155.5 56.63 180 bottom
C359  47uF  [C1206]  145.23 69.8 90 bottom
C360  100nF  [C0402]  143.07 68.28 90 bottom
C361  47uF  [C1206]  140.66 41.49 180 bottom
C362  100nF  [C0603]  140.56 43.23 180 bottom
C365  100nF  [C0201]  35.55 76.74 0 top
C366  100nF  [C0402]  66.05 26.92 270 top
C367  100nF  [C0402]  79.06 27.02 270 top
C368  100nF  [C0402]  88.89 27.46 180 top
C369  100nF  [C0402]  88.48 24.47 270 top
C370  100nF  [C0402]  88.12 34.39 270 top
C371  100nF  [C0402]  88.14 37.83 270 top
C372  100nF  [C0402]  79.18 37.82 90 top
C373  100nF  [C0402]  65.74 37.83 90 top
C374  100nF  [C0402]  75.27 34.39 270 top
C375  100nF  [C0402]  65.74 34.39 90 top
C376  10nF  [C0402]  27.2 31.86 0 bottom
C377  10nF  [C0402]  95.71 32.18 270 top
C378  1uF  [C0402]  27.76 31.73 90 top
C379  1uF  [C0402]  26.77 23.92 90 top
D1  B560C  [DO_214AB]  26.17 104.66 270 top
D3  B560C  [DO_214AB]  135.87 59.65 90 top
D4  B560C  [DO_214AB]  15.89 116.74 90 top
D6  ESD5311X  [ESD0402]  48 50.58 90 bottom
D7  ESD5311X  [ESD0402]  19.83 42.74 0 top
D8  ESD5311X  [ESD0402]  19.85 45.28 0 top
D9  ESD5311X  [ESD0402]  19.86 47.83 0 top
D10  ESD5311X  [ESD0402]  19.84 44.01 0 top
D11  ESD5311X  [ESD0402]  91.67 9.36 0 top
D12  ESD5311X  [ESD0402]  115.95 9.26 0 top
D13  ESD5311X  [ESD0402]  146.96 10.45 270 top
D14  ESD5311X  [ESD0402]  132.67 9.27 0 top
D15  ESD5311X  [ESD0402]  16.1 9.36 0 top
D16  ESD5311X  [ESD0402]  33.55 9.86 90 top
D17  ESD5311X  [ESD0402]  51.97 9.85 90 top
D18  ESD5311X  [ESD0402]  72.03 10.09 90 top
D19  GRN  [LED_0603]  113.41 38.88 0 top
D20  B5819WS  [SOD_323]  21.6 88.15 0 top
D21  B5819WS  [SOD_323]  21.6 90.79 180 top
D22  B5819W  [SOD_123]  13.34 96.96 180 top
D23  ESD5311X  [ESD0402]  74.03 125.59 180 top
D26  ESD5471X  [ESD0402]  17.91 30.54 0 top
D27  ESD5341N  [ESD0402]  17.91 29.44 0 top
D28  ESD5341N  [ESD0402]  17.91 28.34 0 top
D29  ESD5341N  [ESD0402]  17.91 26.14 0 top
D30  ESD5341N  [ESD0402]  17.91 23.99 0 top
D31  ESD5341N  [ESD0402]  17.91 22.9 0 top
D32  ESD5341N  [ESD0402]  17.91 21.8 0 top
D33  PESD12VV1BL  [ESD0402]  78.58 38.59 270 bottom
D34  PESD12VV1BL  [ESD0402]  66.74 38.71 270 bottom
D35  PESD12VV1BL  [ESD0402]  78.58 34.15 270 bottom
D36  PESD12VV1BL  [ESD0402]  66.64 34.07 270 bottom
D37  PESD12VV1BL  [ESD0402]  75.86 22.77 90 bottom
D38  PESD12VV1BL  [ESD0402]  88 22.95 90 bottom
D39  PESD12VV1BL  [ESD0402]  75.87 27.95 90 bottom
D40  PESD12VV1BL  [ESD0402]  87.94 27.91 90 bottom
D41  LED  [LEDX2]  65.43 150.17 180 top
D43  LED  [LEDX2]  93.22 150.19 180 top
D44  1N4148W  [SOD_123]  114.32 14.14 180 top
ED1  ESD5311N  [ESD0402]  35.42 102.93 0 top
ED2  ESD73034D  [SON10_2R50X1R00X0R50]  14.91 82.71 90 top
ED3  ESD73034D  [SON10_2R50X1R00X0R50]  14.91 85.71 90 top
ED4  ESD5341N  [ESD0402]  14.91 91.96 0 top
ED5  ESD5341N  [ESD0402]  14.91 90.89 0 top
ED6  ESD5341N  [ESD0402]  14.91 89.83 0 top
ED7  ESD5341N  [ESD0402]  14.91 87.69 0 top
ED8  ESD5341N  [ESD0402]  14.91 88.76 0 top
ED9  ESD5311N  [ESD0402]  27.74 50.89 0 top
ED10  ESD5311N  [ESD0402]  27.69 49.62 0 top
ED11  ESD5311N  [ESD0402]  27.74 53.34 0 top
ED12  ESD5311N  [ESD0402]  27.74 51.93 0 top
ED13  ESD5341N  [ESD0402]  29.99 65.9 0 top
ED14  ESD5341N  [ESD0402]  29.99 67.3 0 top
ED19  ESD5341N  [ESD0402]  28.27 76.54 0 top
ED20  ESD5341N  [ESD0402]  28.26 77.94 0 top
ED21  PESD12VV1BL  [ESD0402]  17.83 123.53 270 top
ED22  PESD12VV1BL  [ESD0402]  19.09 123.53 270 top
ED23  ESD5311N  [ESD0402]  20.29 123.53 270 top
ED24  ESD5311N  [ESD0402]  21.51 123.53 270 top
ED25  ESD5311N  [ESD0402]  22.72 123.54 270 top
ED26  ESD5311N  [ESD0402]  23.95 123.54 270 top
ED27  PESD12VV1BL  [ESD0402]  27.41 123.56 270 top
ED28  ESD5311N  [ESD0402]  29.78 123.55 270 top
ED29  ESD5311N  [ESD0402]  42.35 123.58 270 top
ED30  ESD5311N  [ESD0402]  40.69 123.57 270 top
ED31  ESD5311N  [ESD0402]  30.98 123.55 270 top
ED32  PESD12VV1BL  [ESD0402]  28.6 123.55 270 top
ED33  PESD12VV1BL  [ESD0402]  38.2 123.56 270 top
ED34  ESD5311N  [ESD0402]  34.59 123.56 270 top
ED35  PESD12VV1BL  [ESD0402]  32.21 123.55 270 top
ED36  PESD12VV1BL  [ESD0402]  39.41 123.56 270 top
ED37  ESD5311N  [ESD0402]  35.82 123.56 270 top
ED38  PESD12VV1BL  [ESD0402]  33.4 123.55 270 top
ED39  ESD5311N  [ESD0402]  45.81 123.57 270 top
ED40  ESD5311N  [ESD0402]  37 123.56 270 top
ED41  ESD5311N  [ESD0402]  52.96 126.07 0 top
ED42  PESD12VV1BL  [ESD0402]  50.7 123.57 270 top
ED43  PESD12VV1BL  [ESD0402]  49.43 123.57 270 top
ED44  SMCJ16CA  [DO-214AB]  5.26 116.93 270 top
ED45  ESD5311N  [ESD0402]  61.36 129.74 270 top
ED46  ESD5311N  [ESD0402]  25.19 123.55 270 top
ED47  PESD12VV1BL  [ESD0402]  43.42 123.57 270 top
ED48  PESD12VV1BL  [ESD0402]  44.61 123.57 270 top
ED49  ESD5311N  [ESD0402]  46.93 123.57 270 top
ED50  ESD5311N  [ESD0402]  48.17 123.57 270 top
F1  UPZ1005D121-1R3TF  [R0402]  109.79 30.28 0 top
F2  UPZ1005D121-1R3TF  [R0402]  94.85 128.96 180 top
FB1  PZ1608U121-2R0TF  [R0603]  116.13 71.18 270 top
FB2  PZ1608U121-2R0TF  [R0603]  114.73 71.19 270 top
FB3  PZ1608U121-2R0TF  [R0603]  117.51 71.17 270 top
FB4  PZ1608U121-2R0TF  [R0603]  3.14 104.58 270 top
FB5  PZ1608U121-2R0TF  [R0603]  1.76 104.6 270 top
FB6  PZ1608U121-2R0TF  [R0603]  122.32 48.13 270 top
FB7  PZ1608U121-2R0TF  [R0603]  120.92 48.14 270 top
FB9  PZ1608U121-2R0TF  [R0603]  113.71 36.06 270 top
FB10  PZ1608U121-2R0TF  [R0603]  137.13 21.51 180 bottom
FB11  PZ1608U121-2R0TF  [R0603]  141.08 31.94 180 bottom
FB12  PZ1608U121-2R0TF  [R0603]  122.63 35.48 0 bottom
FB13  PZ1608U121-2R0TF  [R0603]  116.96 26.72 90 bottom
FB14  PZ1608U121-2R0TF  [R0603]  137.13 20 180 bottom
FB15  PZ1608U121-2R0TF  [R0603]  122.35 18.09 90 bottom
FB16  PZ1608U121-2R0TF  [R0603]  137.88 17.73 270 bottom
FB17  PZ1608U121-2R0TF  [R0603]  140.79 20.1 180 top
FB18  PZ1608U121-2R0TF  [R0603]  32.68 32.34 180 top
FB19  PZ1608U121-2R0TF  [R0603]  52.69 21.37 180 bottom
FB20  PZ1608U121-2R0TF  [R0603]  56.64 31.8 180 bottom
FB21  PZ1608U121-2R0TF  [R0603]  37.9 17.95 90 bottom
FB22  PZ1608U121-2R0TF  [R0603]  32.51 26.58 90 bottom
FB23  PZ1608U121-2R0TF  [R0603]  52.68 19.86 180 bottom
FB24  PZ1608U121-2R0TF  [R0603]  53.43 17.59 270 bottom
FB25  PZ1608U121-2R0TF  [R0603]  58.05 23.16 270 top
FB26  PZ1608U121-2R0TF  [R0603]  38.18 35.34 0 bottom
FB27  PZ1608U121-2R0TF  [R0603]  52.84 119.71 180 top
FB28  PZ1608U121-2R0TF  [R0603]  47.33 111.01 0 top
J1  4 HEADER  [SOCKET_4P_2P54]  93.64 23.8 90 top
J2  APCI0106-P001A  [M2_M_KEY]  31.8 45.01 0 bottom
J4  MICRO SIM  [SIM_002_P6]  8.42 42.64 270 top
J9  C-FKPPR0XD74C  [C_FKPPR0XD]  91.27 4.29 90 top
J10  C-FKPPR0XD74C  [C_FKPPR0XD]  110.51 4.29 90 top
J11  C-FKPPR0XD74C  [C_FKPPR0XD]  129.76 4.29 90 top
J12  C-FKPPR0XD74C  [C_FKPPR0XD]  149 4.29 90 top
J13  C-FKPPR0XD74C  [C_FKPPR0XD]  14.3 4.29 90 top
J14  C-FKPPR0XD74C  [C_FKPPR0XD]  33.54 4.29 90 top
J15  C-FKPPR0XD74C  [C_FKPPR0XD]  52.78 4.29 90 top
J16  C-FKPPR0XD74C  [C_FKPPR0XD]  72.03 4.29 90 top
J17  HDMI_TYPE_A  [HDMIA19_HDMI_01A]  9.53 82.25 90 top
J18  -  [FKPPRNXD06X]  78.13 155.16 180 top
J20  USB30_A_V  [USB30A9_25R70X7R32X13R85]  17 57.67 180 top
J21  USB30_A_V  [USB30A9_25R70X7R32X13R85]  16.98 71.3 180 top
J22  TFP09-2-12B  [TF9_TFP09-2-12B]  7.55 24.05 270 top
J23  4 HEADER  [SOCKET_4P_2P54]  70.44 17.99 0 top
J24  AFC11-S30ICA-00  [FPC30_CAM]  100.64 35.73 180 top
J27  CON8A  [SOCKET_2X4_2P54MM]  141.79 130.14 0 top
J28  CON8A  [SOCKET_2X4_2P54MM]  110.41 130.14 0 top
K1  TS-1185-020E  [SW_3P95MM_3P0MM]  116.15 29.54 90 top
L1  MWSA0603-4R7MT  [L_6030]  133.91 70.24 90 top
L2  MWSA0603-4R7MT  [L_6030]  18.29 106.66 180 top
L3  MWSA0603-4R7MT  [L_6030]  128.39 59.48 180 top
L5  33nH  [L0402]  81.98 145.38 0 top
L6  2.2uH  [L2520]  128.04 82.85 270 top
L7  2.2uH  [L2520]  150.2 83.03 270 top
M1  -  [MARK]  94.77 13.6 0 top
M2  -  [MARK]  151.12 40.91 180 bottom
M3  -  [MARK]  23.41 16.54 0 top
M4  -  [MARK]  151.12 40.91 0 top
M5  -  [MARK]  23.41 16.54 180 bottom
M6  -  [MARK]  94.77 13.6 90 bottom
MH1  HOLE-8STARS  [HOLE_3_5MM]  4.65 155.7 0 top
MH2  HOLE-8STARS  [HOLE_3_5MM]  156.06 10.63 0 top
MH3  HOLE-8STARS  [HOLE_3_5MM]  155.5 155.7 0 top
MH4  HOLE-8STARS  [HOLE_3_5MM]  4.11 4.32 0 top
NOREF  -  []  -0.05 162.51 0 top
NOREF#2  -  []  160.14 0 90 top
Q1  MMBT3904  [SOT_23]  24.25 34.67 270 bottom
Q2  WPM3407-3/TR  [SOT_23]  14.95 40.65 180 bottom
Q3  WPM3407-3/TR  [SOT_23]  49.97 46.45 0 bottom
Q4  MMBT3904  [SOT_23]  14.98 37.5 0 bottom
Q5  MMBT3904  [SOT_23]  30.24 29.88 180 bottom
Q6  MMBT3904  [SOT_23]  114.07 41.04 180 top
Q7  2SK3018  [SOT_323]  20.35 92.86 90 top
Q8  2SK3018  [SOT_323]  20.35 95.4 90 top
Q9  2SK3018  [SOT_323]  18.2 88.81 90 top
Q10  2SK3018  [SOT_323]  24.84 97.85 270 top
Q11  2SK3018  [SOT_323]  20.34 97.88 270 top
Q12  MMBT3904  [SOT_23]  92.52 146.49 0 top
Q14  MMBT3904  [SOT_23]  86.52 38.12 180 bottom
Q15  MMBT3904  [SOT_23]  74.72 38.28 180 bottom
Q16  MMBT3904  [SOT_23]  86.5 33.72 180 bottom
Q17  MMBT3904  [SOT_23]  74.63 33.53 180 bottom
Q18  MMBT3904  [SOT_23]  82.48 38.1 180 bottom
Q19  MMBT3904  [SOT_23]  70.65 38.23 180 bottom
Q20  MMBT3904  [SOT_23]  82.42 33.67 180 bottom
Q21  MMBT3904  [SOT_23]  70.53 33.56 180 bottom
Q22  MMBT3904  [SOT_23]  67.99 23.29 0 bottom
Q23  MMBT3904  [SOT_23]  80.04 23.47 0 bottom
Q24  MMBT3904  [SOT_23]  67.98 28.46 0 bottom
Q25  MMBT3904  [SOT_23]  80.08 28.41 0 bottom
Q26  MMBT3904  [SOT_23]  84.02 23.45 0 bottom
Q27  MMBT3904  [SOT_23]  71.98 23.27 0 bottom
Q28  MMBT3904  [SOT_23]  71.97 28.43 0 bottom
Q29  MMBT3904  [SOT_23]  84.06 28.39 0 bottom
Q30  AO3400  [SOT_23]  57.59 129.33 180 top
Q31  SS8550  [SOT_23]  110.09 14.23 90 top
Q32  MMBT3904  [SOT_23]  27.42 34.72 90 bottom
Q33  MMBT3904  [SOT_23]  98.56 31.43 180 top
R1  100R  [R0402]  37.33 102.91 0 top
R2  100R  [R0402]  42.47 48.84 180 top
R3  18K 1%  [R0402]  144.6 75.27 180 top
R4  20K 1%  [R0402]  144.59 74.27 0 top
R5  33K  [R0402]  140.46 74.79 270 top
R6  47K  [R0402]  147.12 74.77 270 top
R7  200K  [R0402]  146.11 74.76 270 top
R8  10K 1%  [R0402]  143.04 74.77 270 top
R9  12K 1%  [R0402]  33.67 111.73 180 top
R11  100K  [R0402]  2.36 101.64 270 top
R12  20K 1%  [R0402]  33.66 110.74 0 top
R13  200K  [R0402]  36.68 110.71 0 top
R14  10K  [R0402]  8.93 101.51 90 top
R15  20K  [R0402]  29.57 111.26 270 top
R16  100K  [R0402]  36.71 111.72 180 top
R17  200K  [R0402]  35.18 111.23 270 top
R18  10K 1%  [R0402]  32.11 111.24 270 top
R19  12K 1%  [R0402]  144.85 63.61 180 top
R20  40K 1%  [R0402]  144.83 62.72 0 top
R21  2R  [R0603]  10.6 117.86 270 top
R22  200K  [R0402]  147.89 63.34 0 top
R23  33K2  [R0402]  140.94 63.89 270 top
R24  100K  [R0402]  147.91 64.34 180 top
R25  200K  [R0402]  146.36 63.17 270 top
R26  10K 1%  [R0402]  143.36 63.88 270 top
R27  300K 1%  [R0402]  109.01 12.05 90 top
R30  100K  [R0402]  99.77 13.65 270 top
R31  100K 1%  [R0402]  107.01 12.07 270 top
R36  10K  [R0402]  112.87 29.43 90 top
R38  1M  [R0402]  113.88 24.19 90 top
R39  10K/NC  [R0402]  104.68 31.35 180 top
R40  10K  [R0402]  102.16 31.33 0 top
R43  120R  [R0402]  66.06 24.16 270 top
R44  0R  [R0402]  64.55 23.65 0 top
R45  0R  [R0402]  64.55 24.64 0 top
R51  10K  [R0402]  25.74 30.34 90 bottom
R52  10K  [R0402]  44.69 43.7 0 bottom
R53  10K  [R0402]  44.69 44.72 0 bottom
R54  10K  [R0402]  44.69 45.74 0 bottom
R55  1K  [R0402]  24.25 30.9 0 bottom
R56  10K  [R0402]  24.26 31.89 180 bottom
R59  15K  [R0402]  23.59 44.96 180 top
R63  100K  [R0402]  12.07 40.73 270 bottom
R64  100K  [R0402]  52.6 47.13 90 bottom
R65  10K  [R0402]  12.06 38 270 bottom
R66  10K  [R0402]  31.71 31.39 270 bottom
R67  1K  [R0402]  19.72 37.53 90 bottom
R68  1K  [R0402]  27.19 29.85 0 bottom
R69  10K  [R0402]  17.71 37.54 270 bottom
R70  10K  [R0402]  27.19 28.82 180 bottom
R71  0R  [R0402]  91.65 10.43 0 top
R72  0R  [R0402]  132.69 10.34 0 top
R73  75R  [R0402]  93.48 9.79 0 top
R74  0R  [R0402]  115.97 10.33 0 top
R75  0R  [R0402]  145.89 10.34 270 top
R76  75R  [R0402]  117.77 9.67 0 top
R77  75R  [R0402]  115.97 11.32 0 top
R78  75R  [R0402]  91.66 11.43 0 top
R79  75R  [R0402]  132.69 11.34 0 top
R80  75R  [R0402]  144.89 10.35 270 top
R81  75R  [R0402]  134.07 10.9 270 top
R82  75R  [R0402]  143.53 11.41 180 top
R83  1M/NC  [R0402]  120.82 36.57 180 top
R84  22R/NC  [R0402]  120.81 35.55 0 top
R85  22R  [R0402]  120.81 37.58 0 top
R86  4K7  [R0402]  140.45 25.43 180 top
R87  4K7  [R0402]  140.44 26.79 180 top
R88  0R  [R0402]  16.09 10.42 0 top
R89  0R  [R0402]  50.92 9.84 90 top
R90  75R  [R0402]  17.95 10.56 180 top
R91  0R  [R0402]  34.61 9.83 90 top
R92  0R  [R0402]  70.94 10.11 90 top
R93  75R  [R0402]  37.09 9.49 180 top
R94  75R  [R0402]  16.09 11.42 0 top
R95  75R  [R0402]  35.61 9.83 90 top
R96  75R  [R0402]  69.94 10.11 90 top
R97  75R  [R0402]  71.21 11.38 0 top
R98  75R  [R0402]  49.92 9.86 90 top
R99  75R  [R0402]  51.77 11.19 0 top
R100  1K  [R0402]  115.32 39.39 270 top
R101  1M/NC  [R0402]  36.37 36.43 180 top
R102  510R  [R0402]  111.31 41.01 90 top
R103  22R/NC  [R0402]  36.36 35.41 0 top
R104  10K  [R0402]  110.32 41.01 270 top
R105  22R  [R0402]  36.36 37.44 0 top
R106  2K2  [R0402]  55.99 28.65 0 top
R107  2K2  [R0402]  55.99 27.66 180 top
R108  4K7/NC  [R0402]  58.11 25.31 180 top
R109  4K7  [R0402]  56.01 25.29 180 top
R110  4K7  [R0402]  55.99 26.65 180 top
R111  4K7/NC  [R0402]  58.11 26.63 180 top
R112  10K  [R0402]  22.79 92.86 90 top
R113  1.8K  [R0402]  18.15 93.2 270 top
R114  10K  [R0402]  24.26 95.85 180 top
R115  1K  [R0402]  24.26 94.84 180 top
R116  1.8K  [R0402]  18.15 95.24 90 top
R117  27K  [R0402]  21.6 89.47 180 top
R118  27K  [R0402]  18.4 90.79 180 top
R119  47K  [R0402]  26.92 97.85 270 top
R120  47K  [R0402]  22.75 97.85 270 top
R121  1.2K  [R0402]  17.69 96.76 180 top
R122  47K  [R0402]  17.69 97.78 0 top
R123  0R  [R0402]  61.48 135.84 0 top
R124  0R  [R0402]  61.48 134.81 0 top
R125  0R  [R0402]  61.48 136.88 0 top
R126  0R  [R0402]  61.48 137.91 0 top
R127  0R  [R0402]  61.48 139.99 0 top
R128  0R  [R0402]  61.49 138.96 0 top
R129  10K  [R0402]  78.14 139.22 270 top
R130  0R  [R0402]  74.05 124.69 0 top
R131  0R  [R0402]  69.92 154.88 270 top
R132  0R  [R0402]  75.5 149.78 180 top
R133  0R  [R0402]  71.69 128.75 90 top
R134  1K  [R0402]  89.58 147.26 180 top
R135  510R  [R0402]  95.91 146.98 270 top
R136  10K  [R0402]  95.01 146.96 90 top
R137  0R  [R0402]  119.64 95.4 90 top
R138  0R  [R0402]  120.71 95.39 90 top
R140  0R  [R0402]  130.91 87.7 270 top
R141  0R  [R0402]  123.46 95.39 90 top
R142  0R  [R0402]  124.44 95.39 90 top
R143  0R  [R0402]  127.26 95.39 90 top
R145  0R  [R0402]  128.28 95.39 90 top
R146  0R  [R0402]  131.07 95.39 90 top
R147  0R  [R0402]  132.09 95.39 90 top
R148  0R  [R0402]  130.91 89.82 270 top
R150  75R  [R0805]  129.71 113.26 90 bottom
R151  75R  [R0805]  125.9 113.26 90 bottom
R152  75R  [R0805]  122.08 113.26 90 bottom
R153  75R  [R0805]  118.27 113.26 90 bottom
R155  100R  [R0402]  130.91 85.58 90 top
R156  120R  [R0402]  133 85.63 90 top
R157  4.7K  [R0402]  131.95 81.53 270 top
R158  4.7K  [R0402]  132.98 81.53 90 top
R159  4.7K  [R0402]  131.48 83.97 0 top
R160  4.7K  [R0402]  133.28 83.49 90 top
R161  4.7K  [R0402]  131.48 82.97 0 top
R162  2.49K  [R0402]  131.41 91.71 0 top
R163  4.7K  [R0402]  120.97 80.99 270 top
R164  4.7K  [R0402]  120.97 83.43 90 top
R165  4.7K  [R0402]  126.24 83.45 270 top
R166  4.7K  [R0402]  125.19 83.45 270 top
R167  0R/NC  [R0402]  117.67 83.44 270 bottom
R168  4.7K  [R0402]  124.13 80.99 270 top
R169  4.7K  [R0402]  124.13 83.43 90 top
R170  4.7K  [R0402]  123.08 80.99 270 top
R171  4.7K  [R0402]  123.08 83.43 90 top
R172  0R  [R0402]  116.46 90.93 90 top
R173  4.7K  [R0402]  122.02 80.99 270 top
R174  4.7K  [R0402]  122.02 83.43 90 top
R175  4.7K  [R0402]  120.37 91.43 0 top
R176  1.8K  [R0402]  120.37 89.38 0 top
R177  0R  [R0402]  120.37 90.42 0 top
R178  22R  [R0402]  124.13 78.8 270 top
R179  22R  [R0402]  123.08 78.8 270 top
R180  22R  [R0402]  122.02 78.8 270 top
R181  22R  [R0402]  120.97 78.8 270 top
R182  22R  [R0402]  126.24 80.99 270 top
R183  22R  [R0402]  125.19 80.99 270 top
R184  0R  [R0402]  142.6 95.45 90 top
R185  0R  [R0402]  141.53 95.45 90 top
R186  0R  [R0402]  152.94 87.77 270 top
R187  0R  [R0402]  145.35 95.45 90 top
R188  0R  [R0402]  146.33 95.45 90 top
R189  0R  [R0402]  149.15 95.45 90 top
R190  0R  [R0402]  150.17 95.45 90 top
R191  0R  [R0402]  152.96 95.45 90 top
R192  0R  [R0402]  153.98 95.45 90 top
R193  0R  [R0402]  152.94 89.89 270 top
R194  75R  [R0805]  151.6 113.29 90 bottom
R195  75R  [R0805]  147.79 113.29 90 bottom
R196  75R  [R0805]  143.97 113.29 90 bottom
R197  75R  [R0805]  140.16 113.29 90 bottom
R198  22R  [R0402]  152.95 85.65 90 top
R199  120R  [R0402]  155.09 85.66 90 top
R200  4.7K  [R0402]  153.93 81.62 270 top
R201  4.7K  [R0402]  155.12 81.6 90 top
R202  4.7K  [R0402]  153.44 84.12 0 top
R203  4.7K  [R0402]  155.62 84.13 180 top
R204  4.7K  [R0402]  153.44 83.12 0 top
R205  2.49K  [R0402]  153.43 91.73 0 top
R206  4.7K  [R0402]  152.98 81.61 270 top
R207  4.7K  [R0402]  143.09 81.08 270 top
R208  4.7K  [R0402]  143.09 83.52 90 top
R209  4.7K  [R0402]  148.36 83.54 270 top
R210  4.7K  [R0402]  147.3 83.54 270 top
R211  0R  [R0402]  141.87 84.19 90 bottom
R212  4.7K  [R0402]  146.25 81.08 270 top
R213  4.7K  [R0402]  146.25 83.52 90 top
R214  4.7K  [R0402]  145.19 81.08 270 top
R215  4.7K  [R0402]  145.19 83.52 90 top
R216  0R  [R0402]  140.86 84.2 90 bottom
R217  4.7K  [R0402]  144.14 81.08 270 top
R218  4.7K  [R0402]  144.14 83.52 90 top
R219  4.7K  [R0402]  142.53 91.49 0 top
R220  1.8K  [R0402]  142.53 89.36 0 top
R221  0R  [R0402]  142.53 90.48 0 top
R222  22R  [R0402]  146.25 78.61 270 top
R223  22R  [R0402]  145.19 78.61 270 top
R224  22R  [R0402]  144.14 78.61 270 top
R225  22R  [R0402]  143.09 78.61 270 top
R226  22R  [R0402]  148.36 81.08 270 top
R227  22R  [R0402]  147.3 81.08 270 top
R228  2.2R  [R0402]  33.93 65.9 0 top
R229  0R  [R0402]  31.91 65.9 0 top
R230  2.2R  [R0402]  33.91 67.29 0 top
R231  0R  [R0402]  31.92 67.29 0 top
R232  0R  [R0805]  35.71 62.61 180 top
R233  0R  [R0201]  29.37 52.13 180 top
R234  0R  [R0201]  29.37 53.14 180 top
R235  4.7K  [R0402]  35.63 57.35 0 top
R236  10K  [R0402]  38.83 64.71 0 top
R238  20K  [R0402]  38.83 63.68 180 top
R240  0R  [R0402]  30.19 76.54 0 top
R242  0R  [R0402]  30.2 77.94 0 top
R248  4K7  [R0402]  21.75 30.94 270 top
R250  4K7  [R0402]  22.99 31.24 270 top
R252  22R  [R0402]  20.34 21.8 180 top
R253  22R  [R0402]  20.34 22.9 180 top
R254  22R  [R0402]  20.34 23.99 180 top
R255  22R  [R0402]  20.34 28.34 180 top
R256  22R  [R0402]  20.34 29.46 180 top
R257  1K  [R0402]  53.25 112.47 270 top
R258  2K  [R0402]  54.2 114.44 270 top
R260  0R  [R0402]  50.54 120.5 270 top
R261  0R  [R0402]  48.7 120.5 270 top
R262  0R  [R0402]  47.68 120.5 270 top
R263  0R  [R0402]  46.67 120.5 270 top
R264  0R  [R0402]  45.65 120.5 270 top
R265  0R  [R0402]  52.7 117.87 180 top
R266  0R  [R0402]  52.7 116.88 180 top
R267  10K  [R0402]  52.68 115.89 0 top
R268  100R  [R0402]  40.83 121.65 90 top
R269  100R  [R0402]  42.24 121.65 90 top
R270  1K  [R0402]  87.28 36.03 180 bottom
R271  1K  [R0402]  76.03 36.2 180 bottom
R272  1K  [R0402]  87.26 31.64 180 bottom
R273  1K  [R0402]  75.98 31.45 180 bottom
R274  10K  [R0402]  85.27 36.03 180 bottom
R275  10K  [R0402]  73.47 36.2 180 bottom
R276  10K  [R0402]  85.25 31.64 180 bottom
R277  10K  [R0402]  73.39 31.45 180 bottom
R278  1K  [R0402]  67.91 38.76 270 bottom
R279  1K  [R0402]  79.75 34.2 270 bottom
R280  1K  [R0402]  79.74 38.64 270 bottom
R281  1K  [R0402]  67.8 34.12 270 bottom
R282  10K  [R0402]  79.31 37.14 180 bottom
R283  10K  [R0402]  67.48 37.27 180 bottom
R284  10K  [R0402]  79.32 32.7 180 bottom
R285  10K  [R0402]  67.37 32.63 180 bottom
R286  1K  [R0402]  67.23 25.37 0 bottom
R287  1K  [R0402]  79.27 25.55 0 bottom
R288  1K  [R0402]  67.18 30.71 0 bottom
R289  1K  [R0402]  79.3 30.85 0 bottom
R290  10K  [R0402]  69.99 25.38 0 bottom
R291  10K  [R0402]  83 25.55 0 bottom
R292  10K  [R0402]  69.63 30.71 0 bottom
R293  10K  [R0402]  81.89 30.85 0 bottom
R294  1K  [R0402]  86.83 22.9 90 bottom
R295  1K  [R0402]  74.71 27.9 90 bottom
R296  1K  [R0402]  86.77 27.86 90 bottom
R297  1K  [R0402]  74.69 22.72 90 bottom
R298  10K  [R0402]  75.12 24.21 0 bottom
R299  10K  [R0402]  87.26 24.39 0 bottom
R300  10K  [R0402]  75.14 29.4 0 bottom
R301  10K  [R0402]  87.21 29.36 0 bottom
R302  100K  [R0402]  60.26 129.82 90 top
R303  100R  [R0402]  26.27 123.32 90 top
R304  200K  [R0402]  54.92 130.24 90 top
R305  82K  [R0402]  54.92 128.31 90 top
R306  100R  [R0402]  89.24 18.18 0 top
R307  100R  [R0402]  89.25 16.91 0 top
R308  100R  [R0402]  78.34 13.05 180 top
R309  100R  [R0402]  78.34 11.99 180 top
R320  0R  [R1206]  148.65 68.1 0 bottom
R323  1K  [R0402]  60.22 146.53 270 top
R324  1K  [R0402]  61.15 146.53 270 top
R329  10K  [R0402]  35.88 75.88 180 top
R330  10K  [R0402]  35.88 78.59 180 top
R331  20K  [R0402]  35.86 77.6 0 top
R332  0R  [R0402]  77.53 23.85 0 top
R333  120R  [R0402]  79.08 24.36 270 top
R334  0R  [R0402]  77.53 24.87 0 top
R335  0R  [R0402]  77.53 33.67 0 top
R336  120R  [R0402]  79.04 34.19 270 top
R337  0R  [R0402]  77.53 34.71 0 top
R338  0R  [R0402]  76.74 38.46 180 top
R339  120R  [R0402]  75.25 37.92 90 top
R340  0R  [R0402]  76.74 37.44 180 top
R341  10K  [R0402]  114.31 16.61 0 top
R342  2K2  [R0402]  114.32 15.61 180 top
R343  10K  [R0402]  111.87 12.89 0 top
R344  10K  [R0402]  27.2 30.84 0 bottom
R345  10K  [R0402]  29.68 34.81 270 bottom
R346  10K  [R0402]  94.66 32.23 270 top
R347  10K  [R0402]  9.44 103.7 0 top
R348  1K  [R0402]  87.27 147.26 0 top
R349  0R  [R1206]  144.36 40.61 270 bottom
R350  1K  [R0603]  113.99 68.87 0 top
R351  200K  [R0402]  75.35 29.54 180 top
R352  300K  [R0402]  75.28 30.41 0 top
R353  200K  [R0402]  88.79 30.06 180 top
R354  300K  [R0402]  89.8 29.2 180 top
R355  200K  [R0402]  88.75 40.47 180 top
R356  300K  [R0402]  88.74 39.62 0 top
R357  200K  [R0402]  66.04 31.79 90 top
R358  300K  [R0402]  65.55 30.48 0 top
R359  22R  [R0402]  20.13 26.12 180 top
R360  4K7  [R0402]  25.9 23.88 90 top
SW1  TS-1185-020E  [SW_3P95MM_3P0MM]  36.58 100.48 180 top
SW3  SMD  [SMD_2P_5P4X2P9MM]  56.78 121.37 0 top
TP1  TP  [TP_1_0]  117.07 68.9 180 top
TP2  TP  [TP_1_0]  1.3 102.46 180 top
TP3  TP  [TP_1_0]  121.73 45.88 180 top
TP4  TP  [TP_1_0]  22.6 121.77 0 top
TP6  TP  [TP_1_0]  93.27 31.93 90 top
TP7  TP_0.7  [TP_0R70]  130.57 81.75 0 top
U1  U1  [MODLE_65X65MM_256P]  45.23 106.84 270 top
U2  SCT2450STER  [IC_SOP8_PAD]  143.08 70.26 90 top
U3  SCT2650STER  [IC_SOP8_PAD]  34.07 107.15 90 top
U4  TMI6050-18  [SOT_23_5]  6.19 101.1 270 top
U5  SCT2650STER  [IC_SOP8_PAD]  143 59.55 90 top
U6  RT9065  [IC_SOT23_6]  103.43 13.62 270 top
U8  STM32F105RBT6  [IC_QFN64_STM32]  104.42 23.78 90 top
U9  CA-IF1043NF-Q1  [IC_SOIC_14]  70.64 26.08 90 top
U10  CA-IF1043NF-Q1  [IC_SOIC_14]  83.65 26.21 90 top
U11  NVP6188A  [IC_TQFP128]  129.36 27.36 0 top
U12  AMS1117-1.2  [IC_SOT_223_1P2V]  59.99 16.19 270 top
U13  NVP6188A  [IC_TQFP128]  44.91 27.22 0 top
U14  BL-M8852BS2  [IC_BL_M8852BS2]  69.99 138.27 0 top
U15  SKG123NR  [MODEL_SKG123NR]  86.37 137.4 270 top
U16  H5007  [SOIC24_17R53X12R20X5R51]  125.26 105.28 0 top
U17  RTL8211F-CG  [QFN40_5R00X5R00X0R90_T]  125.82 88.41 270 top
U18  H5007  [SOIC24_17R53X12R20X5R51]  147.15 105.31 0 top
U19  RTL8211F-CG  [QFN40_5R00X5R00X0R90_T]  147.86 88.47 270 top
U20  SY6280AAC/TCS9163  [SOT_23_5]  35.7 59.82 270 top
U21  M2_SSD  [M2_SSD_2240_2280]  145.96 45.3 90 bottom
U22  GL835-QFN24-4X4  [IC_QFN24_4X4]  26.5 27.82 180 top
U23  ES8388  [QFN28_4R00X4R00X0R90_T]  48.6 116.52 180 top
U24  0366380002  [SOCKET_PLUG_0366380002]  30.47 135.28 0 top
U25  RS232  [IC_SSOP_16]  83.71 16.27 270 top
U26  CA-IF1043NF-Q1  [IC_SOIC_14]  83.65 36.11 90 top
U28  SGM7228YWQ10  [IC_WQFN_10]  33.21 77.2 180 top
U29  CA-IF1043NF-Q1  [IC_SOIC_14]  70.56 36.11 270 top
X1  32K,12pF  [X_3215_2P]  114.71 19.75 90 top
X2  25M,12pF  [X_3225_2P]  115.88 24.19 90 top
Y1  27MHz/3225/20ppm  [X_3225]  117.13 36.25 90 top
Y2  27MHz/3225/20ppm  [X_3225]  32.68 36.11 90 top
Y3  25MHz  [X_3225]  134.14 88.75 270 top
Y4  25MHz  [X_3225]  156.18 88.82 270 top

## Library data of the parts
C1-C5 C8-C18 C21-C24 C28-C34 C37-C40 C44 C45 C80-C82 C84 C87 C91 C92 C131 C132 C134-C166 C168 C170 C172 C174 C196-C226 C228 C230 C232 C234 C249 C250 C343 C344 C359 C361 C376 C377 = CAP NP_0
C6 C7 C19 C20 C35 C36 C42 C43 C83 C88 C167 C169 C171 C173 C227 C229 C231 C233 = CAP NP_11
C25-C27 C310 C321 C322 C327 C330 C378 C379 = CAP
C41 C79 C89 = CP_0
C46 C56 C57 = CAP 0805
C51 = SC10U10V5ZY_3: room: PWN-IN
C52 = SC100P50V2JN_1: room: PWN-IN
C60-C76 C97-C100 C365-C375 = CAP NP_1
C85 C86 C105-C110 C243-C246 C258-C309 C311-C314 C323 C324 C331-C342 C360 C362 = CAP NP
C96 C247 C248 C251-C257 = CAP NP_6
C111-C130 C133 C175-C195 = CAP NP_2
C235-C242 = CAP NP: signal model: CAP_NP_C0201_220NF_220nF
C325 C326 C328 C329 = C_0
C345-C348 C350 = C_2: signal model: DEFAULT_CAPACITOR_1e+06pF_1_2
C349 = C: signal model: DEFAULT_CAPACITOR_1e+07pF_1_2
C355-C358 = CAP NP: signal model: CAP_NP_C0201_10NF_10nF
D1 D3 D4 = 95SQ015/TO_0
D6-D10 = DIODE BI_DIR TRIG_0
D11-D18 = DIODE BI_DIR TRIG_2
D19 = LED
D20-D22 = DIODE
D23 = DIODE BI_DIR TRIG_1
D26-D32 ED1 ED4-ED14 ED19-ED50 = DIODE BI_DIR TRIG
D33-D40 = DIODE DIAC
D41 D43 = LED_4
D44 = 95SQ015/TO
ED2 ED3 = ESD_ESD5304D
F1 F2 FB1-FB7 FB9-FB28 = FB
J1 J23 = 4 HEADER
J2 = M2_M_KEY_2
J4 = MICRO SIM_0
J9-J16 = CON7
J17 = HDMI_TYPE_A_0
J18 = CON8_1
J20 J21 = USB30_TYPE_A_V_2
J22 = TFCARD_SOCKET
J24 = LD089WU1_0
J27 J28 = CON8A
K1 = SW_PB_SPST
L1-L3 L6 L7 = INDUCTORS OF FERRITE
L5 = INDUCTOR
M1-M6 = MARK
MH1-MH4 = HOLE-8STARS_1
Q1 Q32 Q33 = NPN_0
Q2 Q3 = MOSFET P
Q4 Q5 = NPN
Q6 Q12 = MMBT3904/SOT
Q7-Q11 = MOSFET N
Q14-Q29 = NPN_3
Q30 = 2N6660
Q31 = L14C1/TO_2
R1 R3-R9 R12 R13 R15-R27 R30 R31 R274-R277 R282-R285 R290-R293 R298-R301 R350 = RESISTOR_0
R2 R36 R38-R40 R43-R45 R51-R54 R329 R332-R343 R351-R358 = SR_1
R11 R14 = RES
R55 R56 R59 R248 R250 R344-R347 R360 = RESISTOR_1
R63-R70 R100 R102 R104 R112-R122 R129 R134-R136 R140 R148 R150-R153 R155-R177 R184-R221 R229 R231-R236 R238 R240 R242 R260-R269 R320 R323 R324 R330 R331 R349 R359 = RESISTOR
R71-R99 R101 R103 R105-R111 = RESISTOR_2
R123-R128 = RESISTOR_2: signal model: RESISTOR_2_R0402_0R_0R
R130-R133 = RESISTOR_9
R137 R138 R141-R143 R145-R147 = RESISTOR: signal model: RESISTOR_R0402_0R_0R
R178-R183 R222-R227 R252-R256 = RESISTOR: signal model: RESISTOR_R0402_22R_22R
R228 R230 = RESISTOR: signal model: RESISTOR_R0402_2.2R_2.2R
R257 R258 R306-R309 = R
R270-R273 R278-R281 R286-R289 R294-R297 R302-R305 = R_0
R348 = R_6
SW1 = CAP NP_20
SW3 = SW DIP-4_0
TP1-TP4 TP6 = TP_1
TP7 = TP
U1 = U1_0
U2 U3 U5 = SCT2450STER
U4 = MP2105_1
U6 = TPS79301
U8 = STM32F103CBT6_1
U9 U10 U26 U29 = CA-IF1043NF-Q1
U11 U13 = RAPTOR3_3
U12 = SGM2036-3_4.3YN5G/TR
U14 = BL-M8852BS2
U15 = HX6512_0
U16 U18 = Ethernet_H5007
U17 U19 = Ethernet_RTL8211F
U20 = SWITCH_SY6280
U21 = M2-SSD_1
U22 = GL835 P2P RTS5141_0
U23 = Amplifier_ES8388
U24 = 0366380002
U25 = RS232_0
U28 = SGM7222_1
X1 X2 = ZTB
Y1 Y2 = OSC
Y3 Y4 = CRYSTAL_4P

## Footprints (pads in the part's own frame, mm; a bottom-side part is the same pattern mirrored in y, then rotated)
C0201
  rect 0.25x0.3 smd: 1(-0.275,0) 2(0.275,0)
C0402
  rect 0.55x0.55 smd: 1(-0.45,0) 2(0.45,0)
C0603
  rect 0.8x0.9 smd: 1(-0.7,0) 2(0.7,0)
C0805
  rect 1.41x1.35 smd: 1(-1,0) 2(1,0)
C1206
  rect 1.485x1.728 smd: 1(-1.593,0) 2(1.593,0)
C_FKPPR0XD
  round 1.8 hole 1.15: 1(1.27,4.3) 2(-1.27,4.3) 5(0,0)
  round 2.2 hole 1.6: 3(2.75,2.25) 4(-2.75,2.25) 6(-2.75,-2.25) 7(2.75,-2.25)
DO-214AB
  rect 3.03x3.82 smd: 1(-3.435,0) 2(3.465,0)
DO_214AB
  rect 2.7x3.3 smd: 1(-3.686,0) 2(3.686,0)
ESD0402
  rect 0.5x0.6 smd: 1(-0.4,0) 2(0.4,0)
FKPPRNXD06X
  round 1.1 hole 0.65: 1(-2,2) 2(-2,-2) 3(2,-2) 4(2,2)
  round 2 hole 1.5: 5(-4.35,3.2) 6(-4.35,-3.2) 7(4.35,-3.2) 8(4.35,3.2)
FPC30_CAM
  rect 0.4x1.4 smd: 1(-7.25,-1.2) 2(-6.75,1.2) 3(-6.25,-1.2) 4(-5.75,1.2) 5(-5.25,-1.2) 6(-4.75,1.2) 7(-4.25,-1.2) 8(-3.75,1.2) 9(-3.25,-1.2) 10(-2.75,1.2) 11(-2.25,-1.2) 12(-1.75,1.2) 13(-1.25,-1.2) 14(-0.75,1.2) 15(-0.25,-1.2) 16(0.25,1.2) 17(0.75,-1.2) 18(1.25,1.2) 19(1.75,-1.2) 20(2.25,1.2) 21(2.75,-1.2) 22(3.25,1.2) 23(3.75,-1.2) 24(4.25,1.2) 25(4.75,-1.2) 26(5.25,1.2) 27(5.75,-1.2) 28(6.25,1.2) 29(6.75,-1.2) 30(7.25,1.2)
  rect 2x2.4 smd: 31(9,0) 32(-9,0)
HDMIA19_HDMI_01A
  rect 0.3x2.6 smd: 1(0,0) 2(0.5,0) 3(1,0) 4(1.5,0) 5(2,0) 6(2.5,0) 7(3,0) 8(3.5,0) 9(4,0) 10(4.5,0) 11(5,0) 12(5.5,0) 13(6,0) 14(6.5,0) 15(7,0) 16(7.5,0) 17(8,0) 18(8.5,0) 19(9,0)
  oval 1.5x3.5 hole 0.9x2.7: 20(11.75,0.76) 21(-2.75,0.76)
  oval 1.5x2.5 hole 0.9x1.7: 22(-2.75,6.72) 23(11.75,6.72)
HOLE_3_5MM
  round 6.5 hole 3.2: 1(0,0)
  round 0.762 hole 0.4: 2(2.375,0) 3(1.679,1.679) 4(0,2.375) 5(-1.679,1.679) 6(-2.375,0) 7(-1.679,-1.679) 8(0,-2.375) 9(1.679,-1.679)
IC_BL_M8852BS2
  rect 0.5x1.45 smd: 1(4.5,7.345) 2(3.6,7.345) 3(2.7,7.345) 4(1.8,7.345) 5(0.9,7.345) 6(0,7.345) 7(-0.9,7.345) 8(-1.8,7.345) 9(-2.7,7.345) 10(-3.6,7.345) 11(-4.5,7.345) 26(-4.5,-7.345) 27(-3.6,-7.345) 28(-2.7,-7.345) 29(-1.8,-7.345) 30(-0.9,-7.345) 31(0,-7.345) 32(0.9,-7.345) 33(1.8,-7.345) 34(2.7,-7.345) 35(3.6,-7.345) 36(4.5,-7.345)
  rect 1.45x0.5 smd: 12(-6.325,5.85) 13(-6.325,4.95) 14(-6.325,4.05) 15(-6.325,3.15) 16(-6.325,2.25) 17(-6.325,1.35) 18(-6.325,0.45) 19(-6.325,-0.45) 20(-6.325,-1.35) 21(-6.325,-2.25) 22(-6.325,-3.15) 23(-6.325,-4.05) 24(-6.325,-4.95) 25(-6.325,-5.85) 37(6.325,-5.85) 38(6.325,-4.95) 39(6.325,-4.05) 40(6.325,-3.15) 41(6.325,-2.25) 42(6.325,-1.35) 43(6.325,-0.45) 44(6.325,0.45) 45(6.325,1.35) 46(6.325,2.25) 47(6.325,3.15) 48(6.325,4.05) 49(6.325,4.95) 50(6.325,5.85)
IC_QFN24_4X4
  rect 0.28x0.665 smd: 1(-1.25,-1.908) 2(-0.75,-1.908) 3(-0.25,-1.908) 4(0.25,-1.908) 5(0.75,-1.908) 6(1.25,-1.908) 13(1.25,1.908) 14(0.75,1.908) 15(0.25,1.908) 16(-0.25,1.908) 17(-0.75,1.908) 18(-1.25,1.908)
  rect 0.665x0.28 smd: 7(1.908,-1.25) 8(1.908,-0.75) 9(1.908,-0.25) 10(1.908,0.25) 11(1.908,0.75) 12(1.908,1.25) 19(-1.908,1.25) 20(-1.908,0.75) 21(-1.908,0.25) 22(-1.908,-0.25) 23(-1.908,-0.75) 24(-1.908,-1.25)
  rect 2.55x2.55 smd: 25(0,0)
IC_QFN64_STM32
  oval 0.3x2 smd: 1(-3.75,-5.75) 2(-3.25,-5.75) 3(-2.75,-5.75) 4(-2.25,-5.75) 5(-1.75,-5.75) 6(-1.25,-5.75) 7(-0.75,-5.75) 8(-0.25,-5.75) 9(0.25,-5.75) 10(0.75,-5.75) 11(1.25,-5.75) 12(1.75,-5.75) 13(2.25,-5.75) 14(2.75,-5.75) 15(3.25,-5.75) 16(3.75,-5.75) 33(3.75,5.75) 34(3.25,5.75) 35(2.75,5.75) 36(2.25,5.75) 37(1.75,5.75) 38(1.25,5.75) 39(0.75,5.75) 40(0.25,5.75) 41(-0.25,5.75) 42(-0.75,5.75) 43(-1.25,5.75) 44(-1.75,5.75) 45(-2.25,5.75) 46(-2.75,5.75) 47(-3.25,5.75) 48(-3.75,5.75)
  oval 2x0.3 smd: 17(5.75,-3.75) 18(5.75,-3.25) 19(5.75,-2.75) 20(5.75,-2.25) 21(5.75,-1.75) 22(5.75,-1.25) 23(5.75,-0.75) 24(5.75,-0.25) 25(5.75,0.25) 26(5.75,0.75) 27(5.75,1.25) 28(5.75,1.75) 29(5.75,2.25) 30(5.75,2.75) 31(5.75,3.25) 32(5.75,3.75) 49(-5.75,3.75) 50(-5.75,3.25) 51(-5.75,2.75) 52(-5.75,2.25) 53(-5.75,1.75) 54(-5.75,1.25) 55(-5.75,0.75) 56(-5.75,0.25) 57(-5.75,-0.25) 58(-5.75,-0.75) 59(-5.75,-1.25) 60(-5.75,-1.75) 61(-5.75,-2.25) 62(-5.75,-2.75) 63(-5.75,-3.25) 64(-5.75,-3.75)
IC_SOIC_14
  rect 0.72x1.27 smd: 1(-3.81,-2.86) 2(-2.54,-2.86) 3(-1.27,-2.86) 4(0,-2.86) 5(1.27,-2.86) 6(2.54,-2.86) 7(3.81,-2.86) 8(3.81,2.86) 9(2.54,2.86) 10(1.27,2.86) 11(0,2.86) 12(-1.27,2.86) 13(-2.54,2.86) 14(-3.81,2.86)
IC_SOP8_PAD
  rect 0.61x1.6 smd: 1(-1.905,-2.7) 2(-0.635,-2.7) 3(0.635,-2.7) 4(1.905,-2.7) 5(1.905,2.7) 6(0.635,2.7) 7(-0.635,2.7) 8(-1.905,2.7)
  rect 3.51x2.62 smd: 9(0,0)
IC_SOT23_6
  rect 0.532x1.072 smd: 1(-0.95,-1.149) 2(0,-1.149) 3(0.95,-1.149) 4(0.95,1.149) 5(0,1.149) 6(-0.95,1.149)
